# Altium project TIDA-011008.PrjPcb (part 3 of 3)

## Sheet TIDA-011008_Measurements & AD Buffer.SchDoc
size 431 x 279 mm; Date: Not shown in title block; ApprovedBy: Not shown in title block; CheckedBy: Not shown in title block; Author: Not shown in title block; CompanyName: Not shown in title block; Engineer: Not shown in title block; Organization: Not shown in title block; Address1: Not shown in title block; Address2: Not shown in title block; Address3: Not shown in title block; Address4: Not shown in title block; DocumentNumber: 1; Revision: Use project parameter SCH_Rev; SheetNumber: 7; SheetTotal: 10; PageSetup: Record=PageOptions¦CenterHorizontal=True¦CenterVertical=True¦PrintScale=1.00¦XCorrection=1.00¦YCorrection=1.00¦PrintKind=0¦BorderSize=5000000¦LeftOffset=0¦BottomOffset=0¦Orientation=2¦PaperLength=1000¦PaperWidth=1000¦Scale=100¦PaperSource=15¦PrintQuality=600¦MediaType=1¦DitherType=10¦PaperKind=Letter¦PrintScaleMode=1
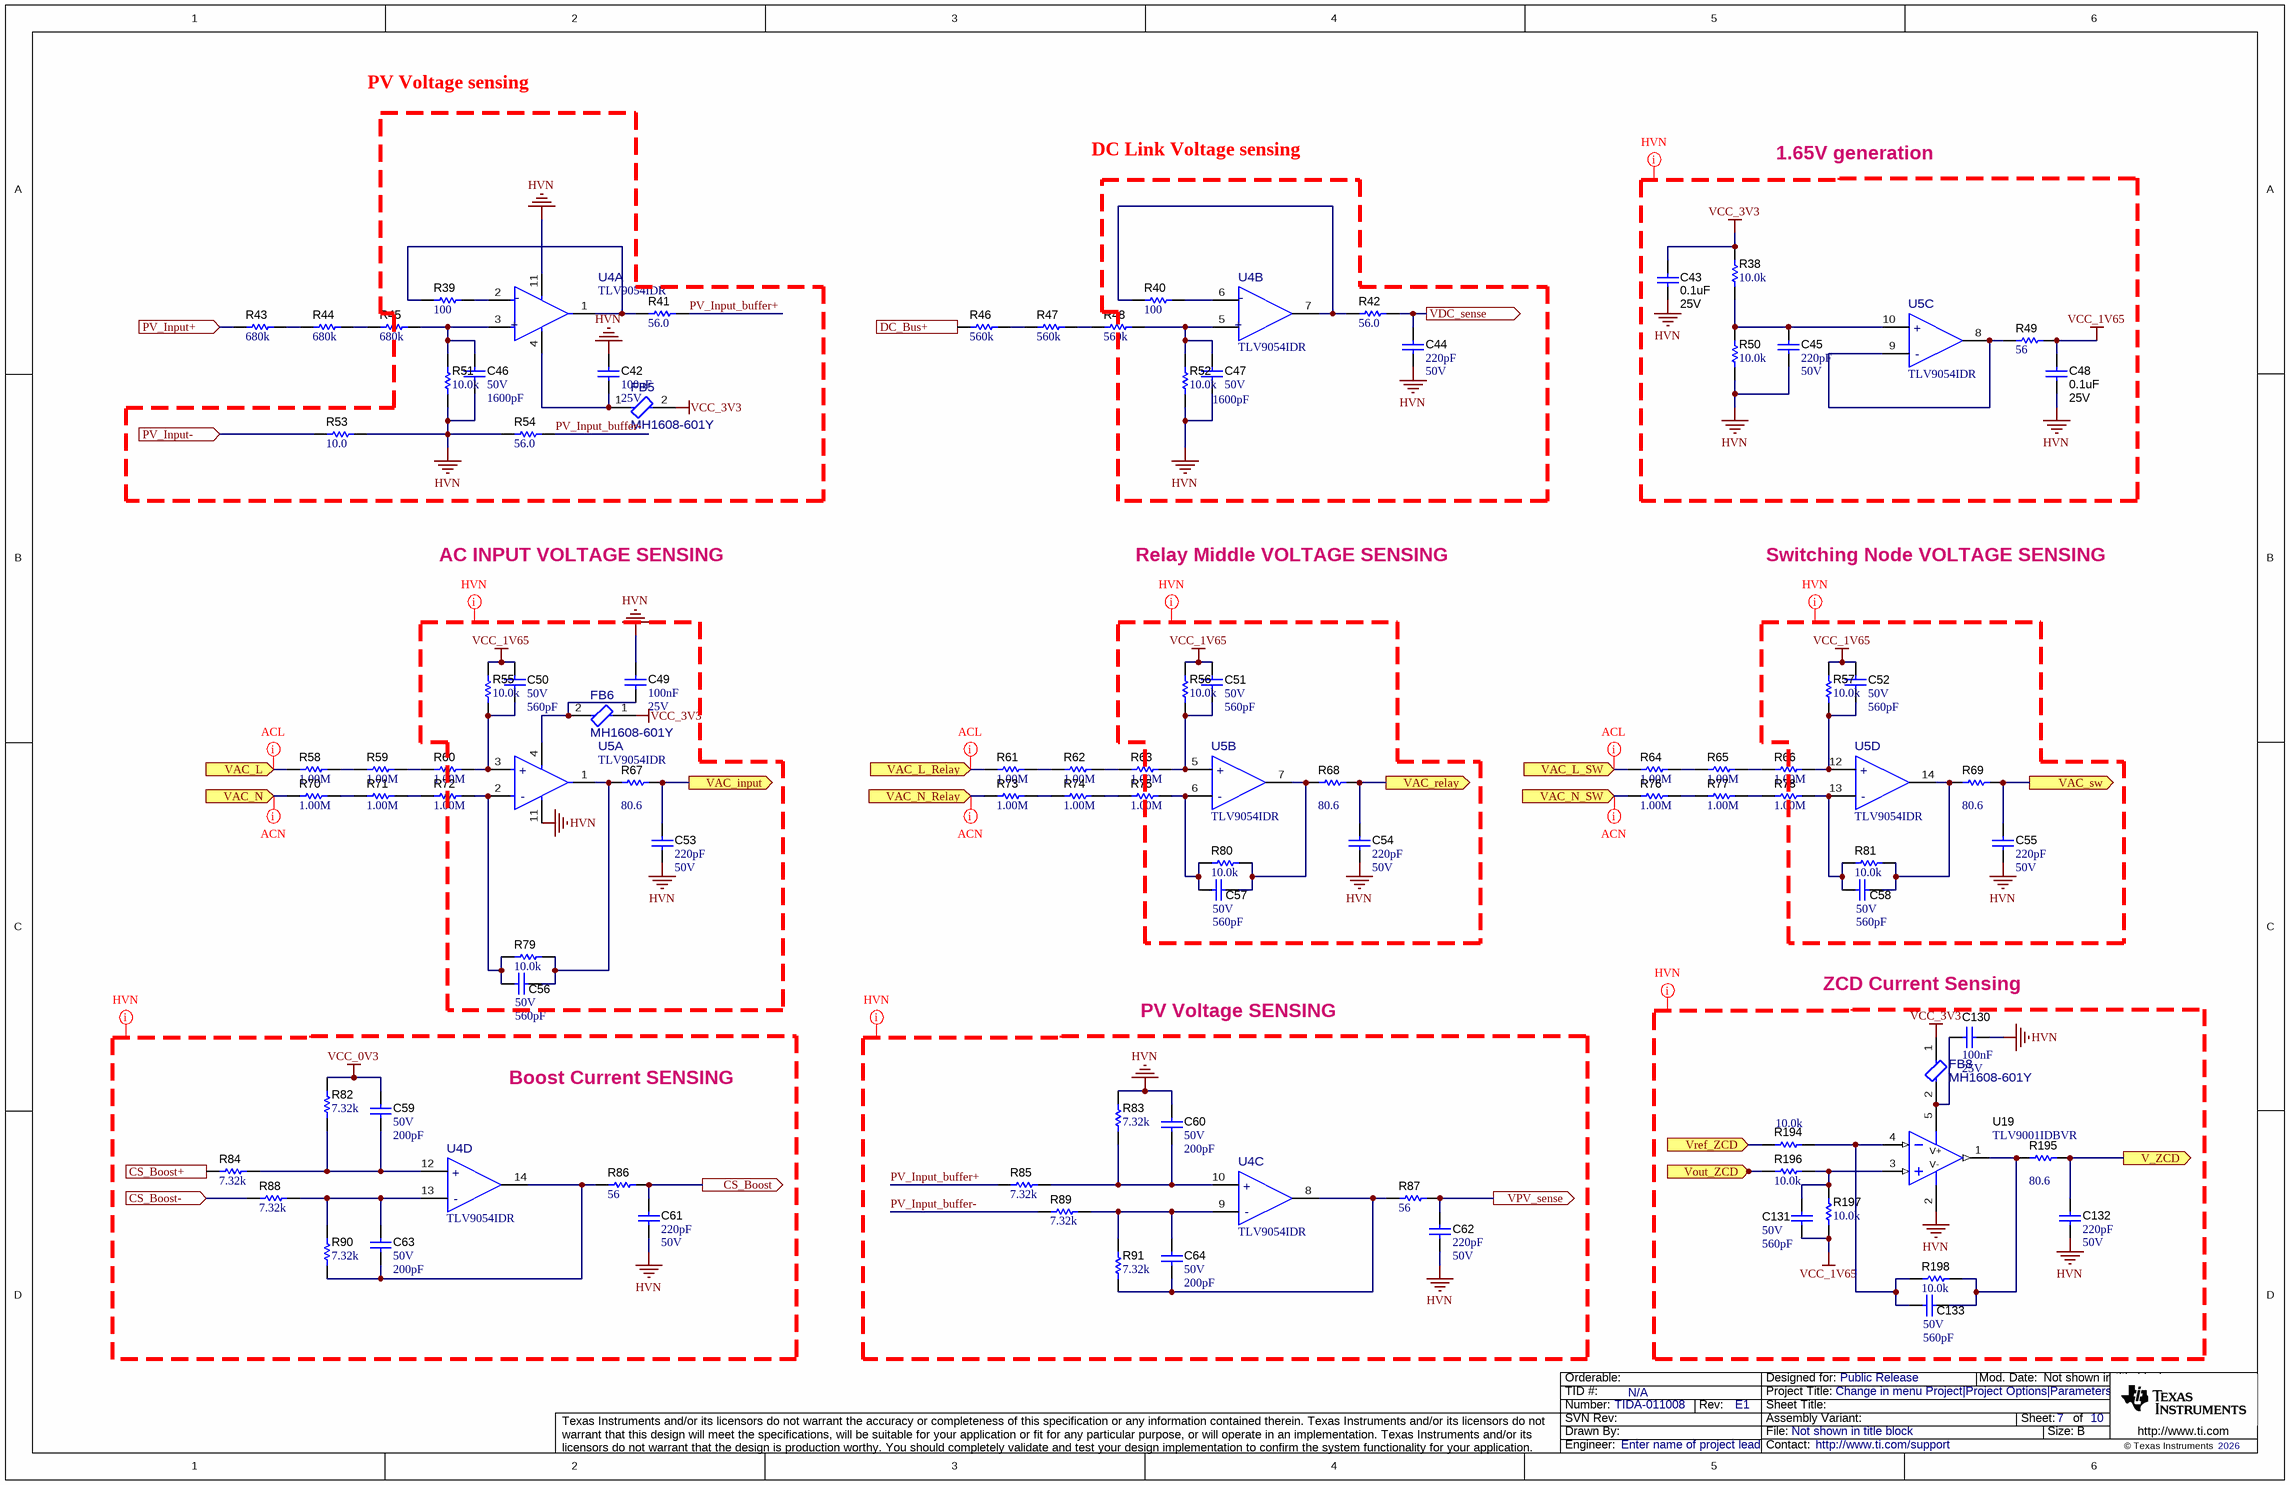
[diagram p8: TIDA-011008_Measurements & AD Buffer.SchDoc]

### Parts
C42  Cap_F: 100nF  VDC_V: 25V  [0603]  (hidden comment: 06033C104JAT2A)
C43  ValueDisplayed: 0.1uF  VDC_V: 25V  [0603]  (hidden comment: C0603X104K3RACTU)
C44  Cap_F: 220pF  VDC_V: 50V  [0603]  (hidden comment: C0603C221K5RACTU)
C45  Cap_F: 220pF  VDC_V: 50V  [0603]  (hidden comment: GRM188R71H221KA01D)
C46  VDC_V: 50V  ValueDisplayed: 1600pF  [0603]  (hidden comment: GRM1885C1H162JA01D)
C47  VDC_V: 50V  ValueDisplayed: 1600pF  [0603]  (hidden comment: GRM1885C1H162JA01D)
C48  ValueDisplayed: 0.1uF  VDC_V: 25V  [0603]  (hidden comment: C0603X104K3RACTU)
C49  Cap_F: 100nF  VDC_V: 25V  [0603]  (hidden comment: 06033C104JAT2A)
C50  VDC_V: 50V  ValueDisplayed: 560pF  [0603]  (hidden comment: GRM1885C1H561JA01D)
C51  VDC_V: 50V  ValueDisplayed: 560pF  [0603]  (hidden comment: GRM1885C1H561JA01D)
C52  VDC_V: 50V  ValueDisplayed: 560pF  [0603]  (hidden comment: GRM1885C1H561JA01D)
C53  Cap_F: 220pF  VDC_V: 50V  [0603]  (hidden comment: GRM188R71H221KA01D)
C54  Cap_F: 220pF  VDC_V: 50V  [0603]  (hidden comment: GRM188R71H221KA01D)
C55  Cap_F: 220pF  VDC_V: 50V  [0603]  (hidden comment: GRM188R71H221KA01D)
C56  VDC_V: 50V  ValueDisplayed: 560pF  [0603]  (hidden comment: GRM1885C1H561JA01D)
C57  VDC_V: 50V  ValueDisplayed: 560pF  [0603]  (hidden comment: GRM1885C1H561JA01D)
C58  VDC_V: 50V  ValueDisplayed: 560pF  [0603]  (hidden comment: GRM1885C1H561JA01D)
C59  VDC_V: 50V  ValueDisplayed: 200pF  [0603]  (hidden comment: GRM1885C1H201JA01D)
C60  VDC_V: 50V  ValueDisplayed: 200pF  [0603]  (hidden comment: GRM1885C1H201JA01D)
C61  Cap_F: 220pF  VDC_V: 50V  [0603]  (hidden comment: GRM188R71H221KA01D)
C62  Cap_F: 220pF  VDC_V: 50V  [0603]  (hidden comment: GRM188R71H221KA01D)
C63  VDC_V: 50V  ValueDisplayed: 200pF  [0603]  (hidden comment: GRM1885C1H201JA01D)
C64  VDC_V: 50V  ValueDisplayed: 200pF  [0603]  (hidden comment: GRM1885C1H201JA01D)
C130  Cap_F: 100nF  VDC_V: 25V  [0603]  (hidden comment: 06033C104JAT2A)
C131  VDC_V: 50V  ValueDisplayed: 560pF  [0603]  (hidden comment: GRM1885C1H561JA01D)
C132  Cap_F: 220pF  VDC_V: 50V  [0603]  (hidden comment: GRM188R71H221KA01D)
C133  VDC_V: 50V  ValueDisplayed: 560pF  [0603]  (hidden comment: GRM1885C1H561JA01D)
FB5  MH1608-601Y  [FP-MH1608-601Y_0603-MFG]
FB6  MH1608-601Y  [FP-MH1608-601Y_0603-MFG]
FB8  MH1608-601Y  [FP-MH1608-601Y_0603-MFG]
R38  ValueDisplayed: 10.0k  [0603]  (hidden comment: RG1608P-103-B-T5)
R39  ValueDisplayed: 100  [0603]  (hidden comment: CRCW0603100RFKEAHP)
R40  ValueDisplayed: 100  [0603]  (hidden comment: CRCW0603100RFKEAHP)
R41  ValueDisplayed: 56.0  [0603]  (hidden comment: RC0603FR-0756RL)
R42  ValueDisplayed: 56.0  [0603]  (hidden comment: RC0603FR-0756RL)
R43  ValueDisplayed: 680k  [1206]  (hidden comment: RC1206FR-07680KL)
R44  ValueDisplayed: 680k  [1206]  (hidden comment: RC1206FR-07680KL)
R45  ValueDisplayed: 680k  [1206]  (hidden comment: RC1206FR-07680KL)
R46  ValueDisplayed: 560k  [1206]  (hidden comment: RC1206FR-07560KL)
R47  ValueDisplayed: 560k  [1206]  (hidden comment: RC1206FR-07560KL)
R48  ValueDisplayed: 560k  [1206]  (hidden comment: RC1206FR-07560KL)
R49  ValueDisplayed: 56  [0603]  (hidden comment: CRCW060356R0JNEA)
R50  ValueDisplayed: 10.0k  [0603]  (hidden comment: RG1608P-103-B-T5)
R51  ValueDisplayed: 10.0k  [0603]  (hidden comment: RCG060310K0FKEA)
R52  ValueDisplayed: 10.0k  [0603]  (hidden comment: RCG060310K0FKEA)
R53  ValueDisplayed: 10.0  [0603]  (hidden comment: RC0603FR-0710RL)
R54  ValueDisplayed: 56.0  [0603]  (hidden comment: RC0603FR-0756RL)
R55  ValueDisplayed: 10.0k  [0603]  (hidden comment: RCG060310K0FKEA)
R56  ValueDisplayed: 10.0k  [0603]  (hidden comment: RCG060310K0FKEA)
R57  ValueDisplayed: 10.0k  [0603]  (hidden comment: RCG060310K0FKEA)
R58  ValueDisplayed: 1.00M  [1206]  (hidden comment: RC1206FR-071ML)
R59  ValueDisplayed: 1.00M  [1206]  (hidden comment: RC1206FR-071ML)
R60  ValueDisplayed: 1.00M  [1206]  (hidden comment: RC1206FR-071ML)
R61  ValueDisplayed: 1.00M  [1206]  (hidden comment: RC1206FR-071ML)
R62  ValueDisplayed: 1.00M  [1206]  (hidden comment: RC1206FR-071ML)
R63  ValueDisplayed: 1.00M  [1206]  (hidden comment: RC1206FR-071ML)
R64  ValueDisplayed: 1.00M  [1206]  (hidden comment: RC1206FR-071ML)
R65  ValueDisplayed: 1.00M  [1206]  (hidden comment: RC1206FR-071ML)
R66  ValueDisplayed: 1.00M  [1206]  (hidden comment: RC1206FR-071ML)
R67  ValueDisplayed: 80.6  [0603]  (hidden comment: RC0603FR-0780R6L)
R68  ValueDisplayed: 80.6  [0603]  (hidden comment: RC0603FR-0780R6L)
R69  ValueDisplayed: 80.6  [0603]  (hidden comment: RC0603FR-0780R6L)
R70  ValueDisplayed: 1.00M  [1206]  (hidden comment: RC1206FR-071ML)
R71  ValueDisplayed: 1.00M  [1206]  (hidden comment: RC1206FR-071ML)
R72  ValueDisplayed: 1.00M  [1206]  (hidden comment: RC1206FR-071ML)
R73  ValueDisplayed: 1.00M  [1206]  (hidden comment: RC1206FR-071ML)
R74  ValueDisplayed: 1.00M  [1206]  (hidden comment: RC1206FR-071ML)
R75  ValueDisplayed: 1.00M  [1206]  (hidden comment: RC1206FR-071ML)
R76  ValueDisplayed: 1.00M  [1206]  (hidden comment: RC1206FR-071ML)
R77  ValueDisplayed: 1.00M  [1206]  (hidden comment: RC1206FR-071ML)
R78  ValueDisplayed: 1.00M  [1206]  (hidden comment: RC1206FR-071ML)
R79  ValueDisplayed: 10.0k  [0603]  (hidden comment: RCG060310K0FKEA)
R80  ValueDisplayed: 10.0k  [0603]  (hidden comment: RCG060310K0FKEA)
R81  ValueDisplayed: 10.0k  [0603]  (hidden comment: RCG060310K0FKEA)
R82  ValueDisplayed: 7.32k  [0603]  (hidden comment: CRCW06037K32FKEA)
R83  ValueDisplayed: 7.32k  [0603]  (hidden comment: CRCW06037K32FKEA)
R84  ValueDisplayed: 7.32k  [0603]  (hidden comment: CRCW06037K32FKEA)
R85  ValueDisplayed: 7.32k  [0603]  (hidden comment: CRCW06037K32FKEA)
R86  ValueDisplayed: 56  [0603]  (hidden comment: CRCW060356R0JNEA)
R87  ValueDisplayed: 56  [0603]  (hidden comment: CRCW060356R0JNEA)
R88  ValueDisplayed: 7.32k  [0603]  (hidden comment: CRCW06037K32FKEA)
R89  ValueDisplayed: 7.32k  [0603]  (hidden comment: CRCW06037K32FKEA)
R90  ValueDisplayed: 7.32k  [0603]  (hidden comment: CRCW06037K32FKEA)
R91  ValueDisplayed: 7.32k  [0603]  (hidden comment: CRCW06037K32FKEA)
R194  ValueDisplayed: 10.0k  [0603]  (hidden comment: RCG060310K0FKEA)
R195  ValueDisplayed: 80.6  [0603]  (hidden comment: RC0603FR-0780R6L)
R196  ValueDisplayed: 10.0k  [0603]  (hidden comment: RCG060310K0FKEA)
R197  ValueDisplayed: 10.0k  [0603]  (hidden comment: RCG060310K0FKEA)
R198  ValueDisplayed: 10.0k  [0603]  (hidden comment: RCG060310K0FKEA)
U4  TLV9054IDR  [D0014A-MFG]  (parts A,B,C,D of 4)
U5  TLV9054IDR  [D0014A-MFG]  (parts A,B,C,D of 4)
U19  TLV9001IDBVR  [DBV0005A_N]

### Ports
CS_Boost (out), CS_Boost+ (in), CS_Boost- (in), DC_Bus+ (in), PV_Input+ (in), PV_Input- (in), V_ZCD (out), VAC_input (out), VAC_L (in), VAC_L_Relay (in), VAC_L_SW (in), VAC_N (in), VAC_N_Relay (in), VAC_N_SW (in), VAC_relay (out), VAC_sw (out), VDC_sense (out), Vout_ZCD (in), VPV_sense (out), Vref_ZCD (in)

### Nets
HVN: C42.1 C43.1 C44.2 C45.1 C46.2 C47.2 C48.1 C49.2 C53.1 C54.1 C55.1 C60.1 C61.1 C62.1 C130.2 C132.1 R50.2 R51.1 R52.1 R53.2 R54.1 R83.2 U4.11(V-) U5.11(V-) U19.2(V-)  [project net DC_Bus-]
VCC_0V3: C59.1 R82.2  [project net CS_Boost_ref]
VCC_1V65: C48.2 C50.2 C51.2 C52.2 C131.2 R49.2 R55.2 R56.2 R57.2 R197.1
VCC_3V3: C43.2 FB5.2 FB6.1 FB8.1 R38.1
CS_Boost: C61.2 R86.2 ; port CS_Boost
CS_Boost+: R84.2 ; port CS_Boost+
CS_Boost-: R88.2 ; port CS_Boost-
DC_Bus+: R46.1 ; port DC_Bus+
PV_Input+: R43.1 ; port PV_Input+
PV_Input-: R53.1 ; port PV_Input-
PV_Input_buffer+: R41.2 R85.2
PV_Input_buffer-: R54.2 R89.2
V_ZCD: C132.2 R195.2 ; port V_ZCD
VAC_input: C53.2 R67.2 ; port VAC_input
VAC_L: R58.1 ; port VAC_L
VAC_L_Relay: R61.1 ; port VAC_L_Relay
VAC_L_SW: R64.1 ; port VAC_L_SW
VAC_N: R70.1 ; port VAC_N
VAC_N_Relay: R73.1 ; port VAC_N_Relay
VAC_N_SW: R76.1 ; port VAC_N_SW
VAC_relay: C54.2 R68.2 ; port VAC_relay
VAC_sw: C55.2 R69.2 ; port VAC_sw
VDC_sense: C44.1 R42.2 ; port VDC_sense
Vout_ZCD: R196.2 ; port Vout_ZCD
VPV_sense: C62.2 R87.2 ; port VPV_sense
Vref_ZCD: R194.2 ; port Vref_ZCD
NetC42_2: C42.2 FB5.1 U4.4(V+)
NetC45_2: C45.2 R38.2 R50.1 U5.10(IN3+)
NetC46_1: C46.1 R45.2 R51.2 U4.3(IN1+)
NetC47_1: C47.1 R48.2 R52.2 U4.5(IN2+)
NetC49_1: C49.1 FB6.2 U5.4(V+)
NetC50_1: C50.1 R55.1 R60.2 U5.3(IN1+)
NetC51_1: C51.1 R56.1 R63.2 U5.5(IN2+)
NetC52_1: C52.1 R57.1 R66.2 U5.12(IN4+)
NetC56_1: C56.1 R67.1 R79.1 U5.1(OUT1)
NetC56_2: C56.2 R72.2 R79.2 U5.2(IN1-)
NetC57_1: C57.1 R68.1 R80.1 U5.7(OUT2)
NetC57_2: C57.2 R75.2 R80.2 U5.6(IN2-)
NetC58_1: C58.1 R69.1 R81.1 U5.14(OUT4)
NetC58_2: C58.2 R78.2 R81.2 U5.13(IN4-)
NetC59_2: C59.2 R82.1 R84.1 U4.12(IN4+)
NetC60_2: C60.2 R83.1 R85.1 U4.10(IN3+)
NetC63_1: C63.1 R88.1 R90.2 U4.13(IN4-)
NetC63_2: C63.2 R86.1 R90.1 U4.14(OUT4)
NetC64_1: C64.1 R89.1 R91.2 U4.9(IN3-)
NetC64_2: C64.2 R87.1 R91.1 U4.8(OUT3)
NetC130_1: C130.1 FB8.2 U19.5(V+)
NetC131_1: C131.1 R196.1 R197.2 U19.3(IN+)
NetC133_1: C133.1 R195.1 R198.1 U19.1(OUT)
NetC133_2: C133.2 R194.1 R198.2 U19.4(IN-)
NetR39_1: R39.1 R41.1 U4.1(OUT1)
NetR39_2: R39.2 U4.2(IN1-)
NetR40_1: R40.1 R42.1 U4.7(OUT2)
NetR40_2: R40.2 U4.6(IN2-)
NetR43_2: R43.2 R44.1
NetR44_2: R44.2 R45.1
NetR46_2: R46.2 R47.1
NetR47_2: R47.2 R48.1
NetR49_1: R49.1 U5.8(OUT3) U5.9(IN3-)
NetR58_2: R58.2 R59.1
NetR59_2: R59.2 R60.1
NetR61_2: R61.2 R62.1
NetR62_2: R62.2 R63.1
NetR64_2: R64.2 R65.1
NetR65_2: R65.2 R66.1
NetR70_2: R70.2 R71.1
NetR71_2: R71.2 R72.1
NetR73_2: R73.2 R74.1
NetR74_2: R74.2 R75.1
NetR76_2: R76.2 R77.1
NetR77_2: R77.2 R78.1

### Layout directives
net class HVN: HVN, PV_Input_buffer+, PV_Input_buffer-, VCC_0V3, VCC_1V65, VCC_3V3
net class ACL: VAC_L, VAC_L_Relay, VAC_L_SW
net class ACN: VAC_N, VAC_N_Relay, VAC_N_SW

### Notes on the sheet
- PV Voltage sensing
- DC Link Voltage sensing
- 1.65V generation
- AC INPUT VOLTAGE SENSING
- Relay Middle VOLTAGE SENSING
- Switching Node VOLTAGE SENSING
- PV Voltage SENSING
- (near C130) ZCD Current Sensing
- Boost Current SENSING

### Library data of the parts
C42 C49 C130 = CMP-0006752-5: CAP, CERM, 0.1 uF, 25 V, +/- 5%, X7R, 0603; Manufacturer: AVX; TaMin_C: -55°C; ESR_ohm: 0.05; Polarized: N; SizeAreaWB_mm2: 4.68; Value1: 0.05 ohm; U/M: EA; Value: 0.1uF; TaMax_C: 125°C; SizeZ_mm: 1; SizeX_mm: 1.6; SizeY_mm: 0.8; SizeArea_mm2: 1.28; AEC Category: Q200
C43 C48 = CMP-0006979-5: CAP, CERM, 0.1 uF, 25 V, +/- 10%, X7R, 0603; Manufacturer: Kemet; Polarized: N; Value: 0.1uF; U/M: EA; Cap_F: 100nF; Value1: Unknown; TaMin_C: -55°C; TaMax_C: 125°C; AEC Category: Q200; SizeArea_mm2: 1.28; SizeAreaWB_mm2: 4.68; SizeX_mm: 1.6; SizeY_mm: 0.8; SizeZ_mm: 1
C44 = CMP-0006895-4: CAP, CERM, 220 pF, 50 V, +/- 10%, X7R, 0603; Manufacturer: Kemet; TaMin_C: -55°C; Polarized: N; SizeAreaWB_mm2: 4.68; Value1: Unknown; U/M: EA; Value: 220pF; TaMax_C: 125°C; SizeZ_mm: 1; SizeX_mm: 1.6; SizeY_mm: 0.8; SizeArea_mm2: 1.28; AEC Category: Q200
C45 C53-C55 C61 C62 C132 = CMP-0007442-5: CAP, CERM, 220 pF, 50 V, +/- 10%, X7R, 0603; Manufacturer: MuRata; TaMin_C: -55°C; Polarized: N; SizeAreaWB_mm2: 4.68; Value1: Unknown; U/M: EA; Value: 220pF; TaMax_C: 125°C; SizeZ_mm: 1; SizeX_mm: 1.6; SizeY_mm: 0.8; SizeArea_mm2: 1.28; AEC Category: Q200
C46 C47 = CMP-0007189-4: CAP, CERM, 1600 pF, 50 V, +/- 5%, C0G/NP0, 0603; Manufacturer: MuRata; TaMin_C: -55°C; Polarized: N; SizeAreaWB_mm2: 4.68; Value1: Unknown; U/M: EA; Value: 1600pF; TaMax_C: 125°C; SizeZ_mm: 1; SizeX_mm: 1.6; SizeY_mm: 0.8; SizeArea_mm2: 1.28; Cap_F: 1.6nF; AEC Category: Q200
C50-C52 C56-C58 C131 C133 = CMP-0007225-4: CAP, CERM, 560 pF, 50 V, +/- 5%, C0G/NP0, 0603; Manufacturer: MuRata; TaMin_C: -55°C; Polarized: N; SizeAreaWB_mm2: 4.68; Value1: Unknown; U/M: EA; Value: 560pF; TaMax_C: 125°C; SizeZ_mm: 1; SizeX_mm: 1.6; SizeY_mm: 0.8; SizeArea_mm2: 1.28; AEC Category: Q200
C59 C60 C63 C64 = CMP-0007194-4: CAP, CERM, 200 pF, 50 V, +/- 5%, C0G/NP0, 0603; Manufacturer: MuRata; TaMin_C: -55°C; Polarized: N; SizeAreaWB_mm2: 4.68; Value1: Unknown; U/M: EA; Value: 200pF; TaMax_C: 125°C; SizeZ_mm: 1; SizeX_mm: 1.6; SizeY_mm: 0.8; SizeArea_mm2: 1.28; AEC Category: Q200
FB5 FB6 FB8 = CMP-0037505-1: 600 Ohms @ 100 MHz 1 Power, Signal Line Ferrite Bead 0603 (1608 Metric) 1A 200mOhm; Manufacturer: Bourns; DCR_ohm: 0.2; SizeZ_mm: 1mm; AEC Qualified: No; Impedance At Frequency: 600Ω @ 100MHz; Test Frequency: 100MHz; Tolerance_%: 25%
R38 R50 = CMP-0023404-3: RES, 10.0 k, 0.1%, 0.1 W, 0603; Manufacturer: Susumu Co Ltd; Power_W: 100mW; TempCo: 25 ppm/C; Value_Code: 10k0; U/M: EA; Value: 10.0k; EIA_Code: E192; Res_ohm: 10k; SizeX_mm: 1.6; SizeY_mm: 0.8; SizeZ_mm: 1; Value2: 0.1W; SizeArea_mm2: 1.28; VDC_V: 75V; AEC Category: Q200
R39 R40 = CMP-0084243-1: RES, 100, 1%, 0.25 W, AEC-Q200 Grade 0, 0603; Manufacturer: Vishay-Dale; Power_W: 250mW; TempCo: 100 ppm/C; SizeAreaWB_mm2: 4.68; Value_Code: 100R; Value: 100; EIA_Code: E96; SizeX_mm: 1.6; SizeY_mm: 0.8; SizeZ_mm: 1; Value2: 0.25W; SizeArea_mm2: 1.28; AEC Qualified: Y; AEC Grade: 0; AEC Category: Q200
R41 R42 R54 = CMP-0023188-5: RES, 56.0, 1%, 0.1 W, 0603; Manufacturer: Yageo; Power_W: 100mW; TempCo: 100 ppm/C; Value_Code: 56R0; Value: 56.0; Res_ohm: 56; SizeX_mm: 1.6; SizeY_mm: 0.8; SizeZ_mm: 1; Value2: 0.1W; SizeArea_mm2: 1.28; AEC Qualified: N; VDC_V: 75V; AEC Category: Q200; SizeAreaWB_mm2: 4.68
R43-R45 = CMP-0018431-2: RES, 680 k, 1%, 0.25 W, 1206; Manufacturer: Yageo America; Power_W: 250mW; TempCo: 100 ppm/C; U/M: EA; Value: 680k; SizeX_mm: 3.2; SizeY_mm: 1.6; SizeZ_mm: 1.35; Value2: 0.25W; SizeArea_mm2: 5.12; VDC_V: 200V; AEC Category: Q200
R46-R48 = CMP-0018373-2: RES, 560 k, 1%, 0.25 W, 1206; Manufacturer: Yageo America; Power_W: 250mW; TempCo: 100 ppm/C; U/M: EA; Value: 560k; SizeX_mm: 3.2; SizeY_mm: 1.6; SizeZ_mm: 1.35; Value2: 0.25W; SizeArea_mm2: 5.12; VDC_V: 200V; AEC Category: Q200
R49 R86 R87 = CMP-0025829-4: RES, 56, 5%, 0.1 W, AEC-Q200 Grade 0, 0603; Manufacturer: Vishay-Dale; Power_W: 100mW; TempCo: 200 ppm/C; Value_Code: 56R0; Value: 56; EIA_Code: E24; SizeX_mm: 1.6; SizeY_mm: 0.8; SizeZ_mm: 1; Value2: 0.1W; SizeArea_mm2: 1.28; AEC Qualified: Y; VDC_V: 75V; AEC Category: Q200; AEC Grade: 0
R51 R52 R55-R57 R79-R81 R194 R196-R198 = CMP-0023337-3: RES, 10.0 k, 1%, 0.1 W, 0603; Manufacturer: Vishay Draloric; Power_W: 100mW; TempCo: 100 ppm/C; Value_Code: 10k0; U/M: EA; Value: 10.0k; EIA_Code: E96; Res_ohm: 10k; SizeX_mm: 1.6; SizeY_mm: 0.8; SizeZ_mm: 1; Value2: 0.1W; SizeArea_mm2: 1.28; AEC Qualified: N; VDC_V: 75V; AEC Category: Q200
R53 = CMP-0022751-4: RES, 10.0, 1%, 0.1 W, 0603; Manufacturer: Yageo; Power_W: 100mW; TempCo: 100 ppm/C; Value_Code: 10R0; Value: 10.0; EIA_Code: E96; Res_ohm: 10; SizeX_mm: 1.6; SizeY_mm: 0.8; SizeZ_mm: 1; Value2: 0.1W; SizeArea_mm2: 1.28; AEC Qualified: N; VDC_V: 75V; AEC Category: Q200; SizeAreaWB_mm2: 4.68
R58-R66 R70-R78 = CMP-0018027-2: RES, 1.00 M, 1%, 0.25 W, 1206; Manufacturer: Yageo America; Power_W: 250mW; TempCo: 100 ppm/C; Value_Code: 1M00; U/M: EA; Value: 1.00Meg; EIA_Code: E96; Res_ohm: 1M; SizeX_mm: 3.2; SizeY_mm: 1.6; SizeZ_mm: 1.35; Value2: 0.25W; SizeArea_mm2: 5.12; VDC_V: 200V; AEC Category: Q200
R67-R69 R195 = CMP-0023286-5: RES, 80.6, 1%, 0.1 W, 0603; Manufacturer: Yageo; Power_W: 100mW; TempCo: 100 ppm/C; Value_Code: 80R6; Value: 80.6; EIA_Code: E96; SizeX_mm: 1.6; SizeY_mm: 0.8; SizeZ_mm: 1; Value2: 0.1W; SizeArea_mm2: 1.28; AEC Qualified: N; VDC_V: 75V; AEC Category: Q200; SizeAreaWB_mm2: 4.68
R82-R85 R88-R91 = CMP-0022600-4: RES, 7.32 k, 1%, 0.1 W, AEC-Q200 Grade 0, 0603; Manufacturer: Vishay-Dale; Power_W: 100mW; TempCo: 100 ppm/C; Value_Code: 7k32; Value: 7.32k; EIA_Code: E96; SizeX_mm: 1.6; SizeY_mm: 0.8; SizeZ_mm: 1; Value2: 0.1W; SizeArea_mm2: 1.28; AEC Qualified: Y; VDC_V: 75V; AEC Category: Q200; AEC Grade: 0
U4 U5 = CMP-0125179-1: Quad 5-MHz, 15-V/µs high slew-rate, RRIO op amp 14-SOIC -40 to 125; Manufacturer: Texas Instruments; SizeZ_mm: 1.75mm; AEC Qualified: No; Gain Bandwidth: 5MHz; Input Bias Current: 2pA; Input Offset Voltage: 0.33mV; Max Dual Supply Voltage: 3V; Max Supply Voltage: 6V; Min Dual Supply Voltage: 900mV; Min Supply Voltage: 1.8V; Nominal Supply Current: 330uA; Number Of Channels: 4; Output Current Per Channel: 50mA; Response Time: 1us; Standoff Height: 0.1mm; TaMax_C: +125°C; TaMin_C: -40°C; TJmax_C: +150°C; Voltage Gain: 130dB
U19 = CMP-0081550-1: Low-Power, Rail-to-Rail In and Out, 1-MHz Operational Amplifier, DBV0005A (SOT-23-5); Alternate PartNumber: TLV9001IDBVT; Alternate Manufacturer: Texas Instruments; SizeAreaWB_mm2: 14.82; SizeZ_mm: 1.45; SizeX_mm: 2.8; SizeY_mm: 2.9; SizeArea_mm2: 8.12; CompType: IC; AEC Qualified: N; AEC Category: Q200

## Sheet TIDA-011008_Hardware.SchDoc
size 431 x 279 mm; Date: Not shown in title block; ApprovedBy: Not shown in title block; CheckedBy: Not shown in title block; Author: Not shown in title block; CompanyName: Not shown in title block; Engineer: Not shown in title block; Organization: Not shown in title block; Address1: Not shown in title block; Address2: Not shown in title block; Address3: Not shown in title block; Address4: Not shown in title block; DocumentNumber: 3; Revision: Use project parameter SCH_Rev; SheetNumber: 3; SheetTotal: 10; PageSetup: Record=PageOptions¦CenterHorizontal=True¦CenterVertical=True¦PrintScale=1.00¦XCorrection=1.00¦YCorrection=1.00¦PrintKind=0¦BorderSize=5000000¦LeftOffset=0¦BottomOffset=0¦Orientation=2¦PaperLength=1000¦PaperWidth=1000¦Scale=100¦PaperSource=15¦PrintQuality=600¦MediaType=1¦DitherType=10¦PaperKind=Letter¦PrintScaleMode=1
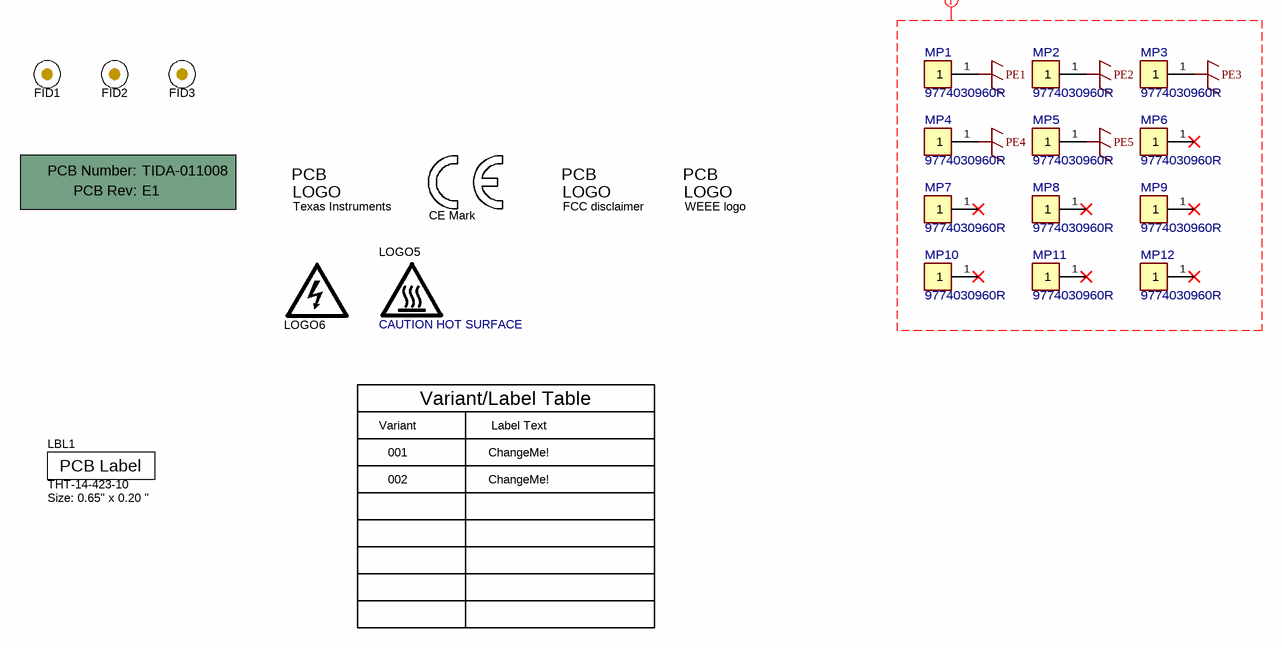
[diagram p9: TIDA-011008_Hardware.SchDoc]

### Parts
!PCB  Printed Circuit Board  (value not drawn)  (mechanical)
FID1  Fiducial  [Fiducial10-20]  (value not drawn)
FID2  Fiducial  [Fiducial10-20]  (value not drawn)
FID3  Fiducial  [Fiducial10-20]  (value not drawn)
LBL1  THT-14-423-10  Note: Size: 0.65" x 0.20 "  [Label_650x200]
Logo1  Texas Instruments  [TI_Stacked_Overlay_Small]  (no BOM)
Logo2  CE Mark  [CE_Mark_5mm]  (no BOM)
Logo3  FCC disclaimer  [FCC_disclaimer]  (no BOM)
Logo4  WEEE logo  [WEEE_Minimum]  (no BOM)
LOGO5  CAUTION HOT SURFACE  [IEC_HotSurface_Medium]  (no BOM)
LOGO6  DANGER HIGH VOLTAGE  [IEC_HighVoltage_Medium]  (value not drawn)  (no BOM)
MP1  9774030960R  [FP-9774030960R_SPACER-MFG]
MP2  9774030960R  [FP-9774030960R_SPACER-MFG]
MP3  9774030960R  [FP-9774030960R_SPACER-MFG]
MP4  9774030960R  [FP-9774030960R_SPACER-MFG]
MP5  9774030960R  [FP-9774030960R_SPACER-MFG]
MP6  9774030960R  [FP-9774030960R_SPACER-MFG]
MP7  9774030960R  [FP-9774030960R_SPACER-MFG]
MP8  9774030960R  [FP-9774030960R_SPACER-MFG]
MP9  9774030960R  [FP-9774030960R_SPACER-MFG]
MP10  9774030960R  [FP-9774030960R_SPACER-MFG]
MP11  9774030960R  [FP-9774030960R_SPACER-MFG]
MP12  9774030960R  [FP-9774030960R_SPACER-MFG]

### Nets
PE1: MP1.1
PE2: MP2.1
PE3: MP3.1
PE4: MP4.1
PE5: MP5.1  [project net PE]

Not connected (* = marked no-connect by the designer): MP6 1*; MP7 1*; MP8 1*; MP9 1*; MP10 1*; MP11 1*; MP12 1*

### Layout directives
net class PE: PE1, PE2, PE3, PE4, PE5

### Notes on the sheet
- Variant
- Variant/Label Table
- Label Text
- 001
- 002
- ChangeMe!

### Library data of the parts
!PCB = CMP-0003618-2: Manufacturer: Any; PartNumber: TIDA-011008
FID1-FID3 = CMP-0077181-1: Fiducial mark.  There is nothing to buy or mount.
LBL1 = CMP-0003625-1: Thermal Transfer Printable Labels, 0.650" W x 0.200" H - 10,000 per roll; Manufacturer: Brady; CompType: Label
Logo1 = CMP-0074838-1: Texas Instrument Corporate Signature; SymbolCreator: a0412235; Lib Reference: TI_Logo; Library Reference: Logo
Logo2 = CMP-0074844-1: SymbolCreator: a0412235
Logo3 = CMP-0074847-1: FCC_disclaimer; Library Reference: Logo
Logo4 = CMP-0074769-1
LOGO5 = CMP-0074837-2: IEC 61010-1 Hot Surface Warning; Manufacturer: Texas Instruments; SymbolCreator: a0412235; AEC Category: Q200; CompType: IC
LOGO6 = CMP-0074835-1: IEC 61010-1 High Voltage Warning; SymbolCreator: a0412235; Lib Reference: IEC_HighVoltage
MP1-MP12 = CMP-0124333-1: Round Spacer Unthreaded Steel 0.118" (3.00mm); Manufacturer: Wurth; AEC Qualified: No; SizeZ_mm: 3.1mm

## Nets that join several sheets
CS_Boost_ref: TIDA-011008_Boost (6 pins), TIDA-011008_Measurements & AD Buffer (C59.1 R82.2)
DC_Bus-: TIDA-011008_CoverSheet (7 pins), TIDA-011008_Boost (24 pins), TIDA-011008_ACDC_EMI Filter (30 pins), TIDA-011008_Aux Power (28 pins), TIDA-011008_Control Stage (52 pins), U_TIDA-011008_ACDC_Leg1 (22 pins), U_TIDA-011008_ACDC_Leg2 (22 pins), TIDA-011008_Measurements & AD Buffer (25 pins)
GND_WiFi: TIDA-011008_Aux Power (J12.10), TIDA-011008_Control Stage (9 pins), TIDA-011008_WiFi Module (21 pins)
PE: TIDA-011008_CoverSheet (J2.1), TIDA-011008_ACDC_EMI Filter (R13.2 R24.1), TIDA-011008_Hardware (MP5.1)
PE1: TIDA-011008_CoverSheet (C7.1), TIDA-011008_Boost (C8.1 C20.2 R2.1 R6.2), TIDA-011008_Hardware (MP1.1)
PE3: TIDA-011008_ACDC_EMI Filter (C25.1 C31.2), TIDA-011008_Hardware (MP3.1)
PE4: TIDA-011008_ACDC_EMI Filter (C24.2 C30.1), TIDA-011008_Hardware (MP4.1)
VCC_1V65: TIDA-011008_Control Stage (R202.2), TIDA-011008_Measurements & AD Buffer (10 pins)
VCC_3V3: TIDA-011008_Boost (FB1.1 R9.2), TIDA-011008_ACDC_EMI Filter (FB4.1 R35.2), TIDA-011008_Aux Power (C72.2 D8.2 TP20.1 U9.5), TIDA-011008_Control Stage (18 pins), U_TIDA-011008_ACDC_Leg1 (C108_U_TIDA-011008_ACDC_Leg1.2 FB7_U_TIDA-011008_ACDC_Leg1.1 U15_U_TIDA-011008_ACDC_Leg1.1), U_TIDA-011008_ACDC_Leg2 (C108_U_TIDA-011008_ACDC_Leg2.2 FB7_U_TIDA-011008_ACDC_Leg2.1 U15_U_TIDA-011008_ACDC_Leg2.1), TIDA-011008_Measurements & AD Buffer (5 pins)
VCC_3V3_WiFi: TIDA-011008_Control Stage (7 pins), TIDA-011008_WiFi Module (11 pins)
VCC_5V: TIDA-011008_ACDC_EMI Filter (5 pins), TIDA-011008_Aux Power (10 pins)
VCC_5V_WiFi: TIDA-011008_Aux Power (J12.9), TIDA-011008_Control Stage (C73.2 U10.3)
VCC_12V: TIDA-011008_Boost (C9.1 R1.1), TIDA-011008_ACDC_EMI Filter (8 pins), TIDA-011008_Aux Power (13 pins), U_TIDA-011008_ACDC_Leg1 (C123_U_TIDA-011008_ACDC_Leg1.1 R171_U_TIDA-011008_ACDC_Leg1.1 R172_U_TIDA-011008_ACDC_Leg1.1 R179_U_TIDA-011008_ACDC_Leg1.1), U_TIDA-011008_ACDC_Leg2 (C123_U_TIDA-011008_ACDC_Leg2.1 R171_U_TIDA-011008_ACDC_Leg2.1 R172_U_TIDA-011008_ACDC_Leg2.1 R179_U_TIDA-011008_ACDC_Leg2.1)
AC_L: TIDA-011008_CoverSheet (J1.1), TIDA-011008_ACDC_EMI Filter (F1.2)
AC_N: TIDA-011008_CoverSheet (J4.1), TIDA-011008_ACDC_EMI Filter (F2.2)
CS_Boost: TIDA-011008_Control Stage (R134.2), TIDA-011008_Measurements & AD Buffer (C61.2 R86.2)
CS_Boost+: TIDA-011008_Boost (C23.1 R8.2 TP8.1), TIDA-011008_Measurements & AD Buffer (R84.2)
CS_Boost-: TIDA-011008_Boost (R11.2 TP10.1), TIDA-011008_Measurements & AD Buffer (R88.2)
DC_Bus+: TIDA-011008_CoverSheet (6 pins), TIDA-011008_Boost (8 pins), TIDA-011008_Aux Power (J12.1), U_TIDA-011008_ACDC_Leg1 (11 pins), U_TIDA-011008_ACDC_Leg2 (11 pins), TIDA-011008_Measurements & AD Buffer (R46.1)
FLT_1A: TIDA-011008_Control Stage (R115.1), U_TIDA-011008_ACDC_Leg1 (U15_U_TIDA-011008_ACDC_Leg1.3)
FLT_1B: TIDA-011008_Control Stage (R159.1), U_TIDA-011008_ACDC_Leg1 (C127_U_TIDA-011008_ACDC_Leg1.2 R181_U_TIDA-011008_ACDC_Leg1.2 U18_U_TIDA-011008_ACDC_Leg1.12)
FLT_2A: TIDA-011008_Control Stage (R118.1), U_TIDA-011008_ACDC_Leg2 (U15_U_TIDA-011008_ACDC_Leg2.3)
FLT_2B: TIDA-011008_Control Stage (R153.1), U_TIDA-011008_ACDC_Leg2 (C127_U_TIDA-011008_ACDC_Leg2.2 R181_U_TIDA-011008_ACDC_Leg2.2 U18_U_TIDA-011008_ACDC_Leg2.12)
FLT_Boost: TIDA-011008_Boost (C15.2 R5.2 U1.12), TIDA-011008_Control Stage (R150.1)
IAC_~{FAULT}: TIDA-011008_ACDC_EMI Filter (C39.2 R33.2), TIDA-011008_Control Stage (R127.2)
IAC_~{OC}: TIDA-011008_ACDC_EMI Filter (C38.2 R32.2), TIDA-011008_Control Stage (R126.2)
IAC_OUT: TIDA-011008_ACDC_EMI Filter (C141.2 FB2.2), TIDA-011008_Control Stage (R132.2)
IAC_REF: TIDA-011008_ACDC_EMI Filter (C140.2 FB3.2), TIDA-011008_Control Stage (R133.2)
PV_Input+: TIDA-011008_CoverSheet (J3.2), TIDA-011008_Boost (L1.2 R2.2 R4.2 TP1.1), TIDA-011008_Measurements & AD Buffer (R43.1)
PV_Input-: TIDA-011008_CoverSheet (J3.1), TIDA-011008_Boost (L1.1 R4.1 R6.1 TP6.1), TIDA-011008_Measurements & AD Buffer (R53.1)
PWM_1A: TIDA-011008_Control Stage (U11.3), U_TIDA-011008_ACDC_Leg1 (R174_U_TIDA-011008_ACDC_Leg1.1)
PWM_1B: TIDA-011008_Control Stage (U11.5), U_TIDA-011008_ACDC_Leg1 (R180_U_TIDA-011008_ACDC_Leg1.1 TP30_U_TIDA-011008_ACDC_Leg1.1)
PWM_2A: TIDA-011008_Control Stage (U11.7), U_TIDA-011008_ACDC_Leg2 (R174_U_TIDA-011008_ACDC_Leg2.1)
PWM_2B: TIDA-011008_Control Stage (U11.9), U_TIDA-011008_ACDC_Leg2 (R180_U_TIDA-011008_ACDC_Leg2.1 TP30_U_TIDA-011008_ACDC_Leg2.1)
PWM_Boost: TIDA-011008_Boost (R3.1 TP4.1), TIDA-011008_Control Stage (U13.3)
Relay_Precharge_mcu: TIDA-011008_ACDC_EMI Filter (C33.1 R28.2 U23.1), TIDA-011008_Control Stage (R146.2)
Relay_Safe_mcu: TIDA-011008_ACDC_EMI Filter (C40.1 R36.2 U24.1), TIDA-011008_Control Stage (R149.2)
SN1: TIDA-011008_ACDC_EMI Filter (J7.1), U_TIDA-011008_ACDC_Leg1 (16 pins)
SN2: TIDA-011008_ACDC_EMI Filter (J9.1), U_TIDA-011008_ACDC_Leg2 (16 pins)
TEMP_SW1: TIDA-011008_Control Stage (R135.2), U_TIDA-011008_ACDC_Leg1 (C120_U_TIDA-011008_ACDC_Leg1.1 R178_U_TIDA-011008_ACDC_Leg1.1)
TEMP_SW2: TIDA-011008_Control Stage (R136.2), U_TIDA-011008_ACDC_Leg2 (C120_U_TIDA-011008_ACDC_Leg2.1 R178_U_TIDA-011008_ACDC_Leg2.1)
UART1_RX: TIDA-011008_Control Stage (J15.3 U22.6), TIDA-011008_WiFi Module (J18.3 R167.1 U14.24)
UART1_TX: TIDA-011008_Control Stage (J15.2 U22.7), TIDA-011008_WiFi Module (J18.2 R168.1 U14.25)
V_ZCD: TIDA-011008_Control Stage (R200.2), TIDA-011008_Measurements & AD Buffer (C132.2 R195.2)
VAC_input: TIDA-011008_Control Stage (R138.2), TIDA-011008_Measurements & AD Buffer (C53.2 R67.2)
VAC_L: TIDA-011008_ACDC_EMI Filter (K2.2 L2.2), TIDA-011008_Measurements & AD Buffer (R58.1)
VAC_L_Relay: TIDA-011008_ACDC_EMI Filter (K1.2 K2.3 R12.2), TIDA-011008_Measurements & AD Buffer (R61.1)
VAC_L_SW: TIDA-011008_ACDC_EMI Filter (K1.3 R12.1 U3.2), TIDA-011008_Measurements & AD Buffer (R64.1)
VAC_N: TIDA-011008_ACDC_EMI Filter (K4.2 L2.1), TIDA-011008_Measurements & AD Buffer (R70.1)
VAC_N_Relay: TIDA-011008_ACDC_EMI Filter (K3.2 K4.3 R25.2), TIDA-011008_Measurements & AD Buffer (R73.1)
VAC_N_SW: TIDA-011008_ACDC_EMI Filter (5 pins), TIDA-011008_Measurements & AD Buffer (R76.1)
VAC_relay: TIDA-011008_Control Stage (R148.2), TIDA-011008_Measurements & AD Buffer (C54.2 R68.2)
VAC_sw: TIDA-011008_Control Stage (R139.2), TIDA-011008_Measurements & AD Buffer (C55.2 R69.2)
VDC_sense: TIDA-011008_Control Stage (R140.2), TIDA-011008_Measurements & AD Buffer (C44.1 R42.2)
Vout_ZCD: TIDA-011008_ACDC_EMI Filter (U20.1), TIDA-011008_Measurements & AD Buffer (R196.2)
VPV_sense: TIDA-011008_Control Stage (R141.2), TIDA-011008_Measurements & AD Buffer (C62.2 R87.2)
Vref_ZCD: TIDA-011008_ACDC_EMI Filter (U20.5), TIDA-011008_Measurements & AD Buffer (R194.2)
ZCD_CHK: TIDA-011008_ACDC_EMI Filter (R201.1), TIDA-011008_Control Stage (R199.2)

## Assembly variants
001: not fitted C7 C9 C110_U_TIDA-011008_ACDC_Leg1 C110_U_TIDA-011008_ACDC_Leg2 C123_U_TIDA-011008_ACDC_Leg1 C123_U_TIDA-011008_ACDC_Leg2 J18 J19 R? R?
